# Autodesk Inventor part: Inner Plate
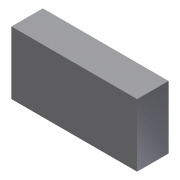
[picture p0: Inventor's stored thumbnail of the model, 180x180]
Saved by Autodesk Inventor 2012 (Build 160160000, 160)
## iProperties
Created: 2010-04
Part Number: Inner Plate
Document SubType Name: Modeling
Designer: CADSoft
Density: 1 g/cm^3
Material: Default
Author: CADSoft
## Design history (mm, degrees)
sketch "Sketch1"
  geometry: L1 (-20.23, -7.511)-(19.77, -7.511); L2 (19.77, -7.511)-(19.77, 12.489); L3 (19.77, 12.489)-(-20.23, 12.489); L4 (-20.23, 12.489)-(-20.23, -7.511); 1 further point
  constraints: 8 end point, 2 parallel, 1 horizontal, 1 perpendicular
workplane "Work Plane1"
extrude "Extrusion1" new body sketch "Sketch1" stored distance "d0" = 25.4; taper "d1" = 0 deg
body "Solid1"
